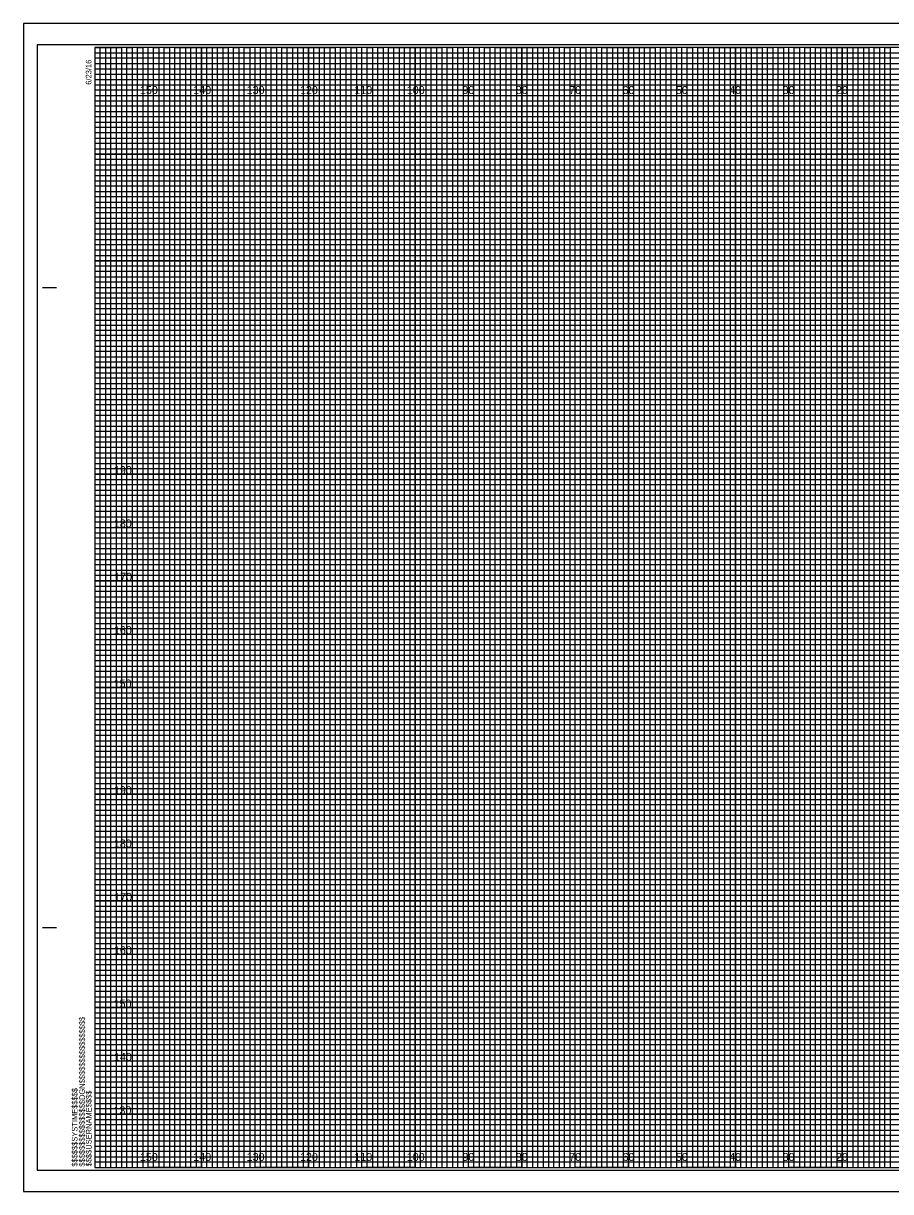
# Model space of a CAD drawing. Extents: x -13 to 323, y -5 to 4174.
# Drawn here: x -13.4 to 149.1, y 655.5 to 874.5 of the extents above; entities that cross this region are included whole.
import ezdxf

# ---------------------------------------------------------------- set-up
doc = ezdxf.new("R2010")
doc.units = 0
for name, color, linetype in [('Exist Cross Section Cell', 7, 'Continuous'), ('Exist XS Center Line Elevation Label', 7, 'Continuous'), ('Exist XS Ground Line', 7, 'Continuous'), ('Prop CMT Guardrail Graphics', 7, 'Continuous'), ('Prop CMT Pvmt Course 1', 7, 'Continuous'), ('Prop CMT Pvmt Course 2', 7, 'Continuous'), ('Prop CMT Pvmt Course 3', 7, 'Continuous'), ('Prop CMT Shld Paved Course 1', 7, 'Continuous'), ('Prop CMT Shld Paved Course 2', 7, 'Continuous'), ('Prop CMT Subgrade Earthwork', 7, 'Continuous'), ('Scratch_Level_0', 7, 'Continuous')]:
    doc.layers.add(name, color=color, linetype=linetype)

msp = doc.modelspace()

# ---------------------------------------------------------------- linework, layer by layer
at = {"layer": 'Exist XS Center Line Elevation Label'}
for points in [[(0, 870), (5, 870), (5, 660), (15, 660), (15, 870), (25, 870), (25, 660), (35, 660), (35, 870), (45, 870), (45, 660), (55, 660), (55, 870), (65, 870), (65, 660), (75, 660), (75, 870), (85, 870), (85, 660), (95, 660), (95, 870), (105, 870), (105, 660), (115, 660), (115, 870), (125, 870), (125, 660), (135, 660), (135, 870), (145, 870), (145, 660), (155, 660)], [(0, 865), (275, 865)], [(0, 845), (320, 845), (320, 855), (0, 855)], [(0, 825), (320, 825), (320, 835), (0, 835)], [(0, 805), (320, 805), (320, 815), (0, 815)], [(0, 785), (320, 785), (320, 795), (0, 795)], [(0, 765), (320, 765), (320, 775), (0, 775)], [(0, 745), (320, 745), (320, 755), (0, 755)], [(0, 725), (320, 725), (320, 735), (0, 735)], [(0, 705), (320, 705), (320, 715), (0, 715)], [(0, 685), (320, 685), (320, 695), (0, 695)], [(0, 665), (320, 665), (320, 675), (0, 675)]]:
    msp.add_lwpolyline(points, dxfattribs=at)
at = {"layer": 'Exist XS Ground Line'}
for p, q in [((10, 870), (0, 870)), ((10, 660), (10, 870)), ((30, 870), (20, 870)), ((20, 870), (20, 660)), ((30, 660), (30, 870)), ((50, 870), (40, 870)), ((40, 870), (40, 660)), ((50, 660), (50, 870)), ((70, 870), (60, 870)), ((60, 870), (60, 660)), ((70, 660), (70, 870)), ((90, 870), (80, 870)), ((80, 870), (80, 660)), ((90, 660), (90, 870)), ((110, 870), (100, 870)), ((100, 870), (100, 660)), ((110, 660), (110, 870)), ((130, 870), (120, 870)), ((120, 870), (120, 660)), ((130, 660), (130, 870)), ((150, 870), (140, 870)), ((140, 870), (140, 660)), ((20, 660), (10, 660)), ((40, 660), (30, 660)), ((60, 660), (50, 660)), ((80, 660), (70, 660)), ((100, 660), (90, 660)), ((120, 660), (110, 660)), ((140, 660), (130, 660))]:
    msp.add_line(p, q, dxfattribs=at)
for points in [[(0, 860), (320, 860), (320, 850), (0, 850)], [(0, 840), (320, 840), (320, 830), (0, 830)], [(0, 820), (320, 820), (320, 810), (0, 810)], [(0, 800), (320, 800), (320, 790), (0, 790)], [(0, 780), (320, 780), (320, 770), (0, 770)], [(0, 760), (320, 760), (320, 750), (0, 750)], [(0, 740), (320, 740), (320, 730), (0, 730)], [(0, 720), (320, 720), (320, 710), (0, 710)], [(0, 700), (320, 700), (320, 690), (0, 690)], [(0, 680), (320, 680), (320, 670), (0, 670)]]:
    msp.add_lwpolyline(points, dxfattribs=at)
at = {"layer": 'Prop CMT Pvmt Course 1'}
for p, q in [((323.3, 874.5), (-13.4, 874.5)), ((-13.4, 874.5), (-13.4, 655.5)), ((-13.4, 655.5), (323.3, 655.5))]:
    msp.add_line(p, q, dxfattribs=at)
at = {"layer": 'Prop CMT Pvmt Course 2'}
msp.add_lwpolyline([(-13.4, 655.5), (323.3, 655.5), (323.3, 874.5), (-13.4, 874.5)], close=True, dxfattribs=at)
at = {"layer": 'Prop CMT Pvmt Course 3'}
msp.add_lwpolyline([(-10.8, 659.5), (322.4, 659.5), (322.4, 870.5), (-10.8, 870.5)], close=True, dxfattribs=at)
at = {"layer": 'Prop CMT Shld Paved Course 1'}
for p, q in [((-9.8, 825), (-7.3, 825)), ((-9.7, 825), (-7.2, 825)), ((-9.8, 705), (-7.3, 705)), ((-9.7, 705), (-7.2, 705)), ((0, 660), (0, 660)), ((0, 660), (0, 660)), ((0, 660), (0, 660)), ((0, 660), (0, 660)), ((0, 660), (0, 660)), ((0, 660), (0, 660)), ((0, 660), (0, 660))]:
    msp.add_line(p, q, dxfattribs=at)
msp.add_lwpolyline([(320, 870), (0, 870), (0, 660), (320, 660)], close=True, dxfattribs=at)
at = {"layer": 'Prop CMT Shld Paved Course 2'}
for points in [[(0, 660), (1, 660), (1, 870), (2, 870), (2, 660)], [(2, 660), (3, 660), (3, 870), (4, 870), (4, 660)], [(5, 660), (6, 660), (6, 870), (7, 870), (7, 660)], [(7, 660), (8, 660), (8, 870), (9, 870), (9, 660)], [(10, 660), (11, 660), (11, 870), (12, 870), (12, 660)], [(12, 660), (13, 660), (13, 870), (14, 870), (14, 660)], [(15, 660), (16, 660), (16, 870), (17, 870), (17, 660)], [(17, 660), (18, 660), (18, 870), (19, 870), (19, 660)], [(20, 660), (21, 660), (21, 870), (22, 870), (22, 660)], [(22, 660), (23, 660), (23, 870), (24, 870), (24, 660)], [(25, 660), (26, 660), (26, 870), (27, 870), (27, 660)], [(27, 660), (28, 660), (28, 870), (29, 870), (29, 660)], [(30, 660), (31, 660), (31, 870), (32, 870), (32, 660)], [(32, 660), (33, 660), (33, 870), (34, 870), (34, 660)], [(35, 660), (36, 660), (36, 870), (37, 870), (37, 660)], [(37, 660), (38, 660), (38, 870), (39, 870), (39, 660)], [(40, 660), (41, 660), (41, 870), (42, 870), (42, 660)], [(42, 660), (43, 660), (43, 870), (44, 870), (44, 660)], [(45, 660), (46, 660), (46, 870), (47, 870), (47, 660)], [(47, 660), (48, 660), (48, 870), (49, 870), (49, 660)], [(50, 660), (51, 660), (51, 870), (52, 870), (52, 660)], [(52, 660), (53, 660), (53, 870), (54, 870), (54, 660)], [(55, 660), (56, 660), (56, 870), (57, 870), (57, 660)], [(57, 660), (58, 660), (58, 870), (59, 870), (59, 660)], [(60, 660), (61, 660), (61, 870), (62, 870), (62, 660)], [(62, 660), (63, 660), (63, 870), (64, 870), (64, 660)], [(65, 660), (66, 660), (66, 870), (67, 870), (67, 660)], [(67, 660), (68, 660), (68, 870), (69, 870), (69, 660)], [(70, 660), (71, 660), (71, 870), (72, 870), (72, 660)], [(72, 660), (73, 660), (73, 870), (74, 870), (74, 660)], [(75, 660), (76, 660), (76, 870), (77, 870), (77, 660)], [(77, 660), (78, 660), (78, 870), (79, 870), (79, 660)], [(80, 660), (81, 660), (81, 870), (82, 870), (82, 660)], [(82, 660), (83, 660), (83, 870), (84, 870), (84, 660)], [(85, 660), (86, 660), (86, 870), (87, 870), (87, 660)], [(87, 660), (88, 660), (88, 870), (89, 870), (89, 660)], [(90, 660), (91, 660), (91, 870), (92, 870), (92, 660)], [(92, 660), (93, 660), (93, 870), (94, 870), (94, 660)], [(95, 660), (96, 660), (96, 870), (97, 870), (97, 660)], [(97, 660), (98, 660), (98, 870), (99, 870), (99, 660)], [(100, 660), (101, 660), (101, 870), (102, 870), (102, 660)], [(102, 660), (103, 660), (103, 870), (104, 870), (104, 660)], [(105, 660), (106, 660), (106, 870), (107, 870), (107, 660)], [(107, 660), (108, 660), (108, 870), (109, 870), (109, 660)], [(110, 660), (111, 660), (111, 870), (112, 870), (112, 660)], [(112, 660), (113, 660), (113, 870), (114, 870), (114, 660)], [(115, 660), (116, 660), (116, 870), (117, 870), (117, 660)], [(117, 660), (118, 660), (118, 870), (119, 870), (119, 660)], [(120, 660), (121, 660), (121, 870), (122, 870), (122, 660)], [(122, 660), (123, 660), (123, 870), (124, 870), (124, 660)], [(125, 660), (126, 660), (126, 870), (127, 870), (127, 660)], [(127, 660), (128, 660), (128, 870), (129, 870), (129, 660)], [(130, 660), (131, 660), (131, 870), (132, 870), (132, 660)], [(132, 660), (133, 660), (133, 870), (134, 870), (134, 660)], [(135, 660), (136, 660), (136, 870), (137, 870), (137, 660)], [(137, 660), (138, 660), (138, 870), (139, 870), (139, 660)], [(140, 660), (141, 660), (141, 870), (142, 870), (142, 660)], [(142, 660), (143, 660), (143, 870), (144, 870), (144, 660)], [(145, 660), (146, 660), (146, 870), (147, 870), (147, 660)], [(147, 660), (148, 660), (148, 870), (149, 870), (149, 660)]]:
    msp.add_lwpolyline(points, dxfattribs=at)
at = {"layer": 'Prop CMT Subgrade Earthwork'}
for p, q in [((10, 660), (10, 870)), ((20, 660), (20, 870)), ((30, 660), (30, 870)), ((40, 660), (40, 870)), ((50, 660), (50, 870)), ((60, 660), (60, 870)), ((70, 660), (70, 870)), ((80, 660), (80, 870)), ((90, 660), (90, 870)), ((100, 660), (100, 870)), ((110, 660), (110, 870)), ((120, 660), (120, 870)), ((130, 660), (130, 870)), ((140, 660), (140, 870)), ((0, 860), (320, 860)), ((0, 850), (320, 850)), ((0, 840), (320, 840)), ((0, 830), (320, 830)), ((0, 820), (320, 820)), ((0, 810), (320, 810)), ((0, 800), (320, 800)), ((0, 790), (320, 790)), ((0, 780), (320, 780)), ((0, 770), (320, 770)), ((0, 760), (320, 760)), ((0, 750), (320, 750)), ((0, 740), (320, 740)), ((0, 730), (320, 730)), ((0, 720), (320, 720)), ((0, 710), (320, 710)), ((0, 700), (320, 700)), ((0, 690), (320, 690)), ((0, 680), (320, 680)), ((0, 670), (320, 670))]:
    msp.add_line(p, q, dxfattribs=at)
at = {"layer": 'Scratch_Level_0'}
for p, q in [((0, 869), (260, 869)), ((260, 867.98), (0, 867.98)), ((0, 867.98), (0, 867)), ((0, 867), (260, 867)), ((260, 865.89), (0, 865.89)), ((0, 865.89), (0, 864)), ((0, 864), (320, 864))]:
    msp.add_line(p, q, dxfattribs=at)
for points in [[(0, 863), (270, 863), (320, 863), (320, 862), (0, 862)], [(0, 861), (320, 861), (320, 859), (0, 859)], [(0, 858), (320, 858), (320, 857), (0, 856.98)], [(0, 856), (320, 856), (320, 854), (0, 854)], [(0, 853), (320, 853), (320, 852), (0, 852)], [(0, 851), (320, 851), (320, 849), (0, 849)], [(0, 848), (320, 848), (320, 847), (0, 847)], [(0, 846), (320, 846), (320, 844), (0, 844)], [(0, 843), (320, 843), (320, 842), (0, 842)], [(0, 841), (320, 841), (320, 839), (0, 839)], [(0, 838), (320, 838), (320, 837), (0, 837)], [(0, 836), (320, 836), (320, 833.95), (320, 833), (320, 832), (0, 832)], [(0, 834), (320, 834), (320, 833), (0, 833)], [(0, 831), (320, 831), (320, 829), (0, 829.03)], [(0, 829.03), (320, 829), (320, 828), (0, 828)], [(0, 827), (320, 827), (320, 826), (0, 826)], [(0, 824), (320, 824), (320, 823), (0, 823)], [(0, 822), (320, 822), (320, 821), (0, 821)], [(-0.07, 818.89), (320, 818.89), (320, 817.88), (-0.07, 817.88)], [(0, 817), (320, 817), (320, 816), (0, 816)], [(0, 814), (320, 814), (320, 813), (0, 813)], [(0, 812), (320, 812), (320, 811), (0, 811)], [(0, 809), (320, 809), (320, 808), (0, 808)], [(0, 807), (320, 807), (320, 806), (0, 806)], [(0, 804), (320, 804), (320, 803), (0, 803)], [(0, 802), (320, 802), (320, 801), (0, 801)], [(0, 799), (320, 799), (319.99, 797.98), (0, 798)], [(0, 797), (320, 797), (320, 796), (0, 796)], [(0, 794), (320, 794), (320, 793), (0, 793)], [(0, 792), (320, 792), (320, 791), (0, 791)], [(0, 789), (320, 789), (320, 788), (0, 788)], [(0, 787), (320, 787), (320, 786), (0, 786)], [(0, 784), (320, 784), (320, 783), (0, 783)], [(0, 782), (320, 782), (320, 781), (0, 781)], [(0, 779), (320, 779), (320, 778), (0, 778)], [(0, 776.99), (320.07, 776.91), (320, 776), (0, 776)], [(0, 774), (320, 774), (320, 773), (0, 773)], [(0, 772), (320, 772), (320, 771), (0, 771)], [(0, 769), (320, 769), (320, 768), (0, 768)], [(0, 767), (320, 767), (320, 766), (0, 766)], [(0, 764), (320, 764), (320, 763), (0, 763)], [(0, 762), (320, 762), (320, 761), (0, 761)], [(0, 759), (320, 759), (320, 758), (0, 758)], [(0, 757), (320, 757), (320, 756), (0, 756)], [(0, 754), (320, 754), (320, 753), (0, 753)], [(0, 752), (320, 752), (320, 751), (0, 751)], [(0, 749), (320, 749), (320, 748), (0, 748)], [(0, 747), (320, 747), (320, 746), (0, 746)], [(0, 744), (320, 744), (320, 743), (0, 743)], [(0, 742), (320, 742), (320, 741), (0, 741)], [(0, 739), (320, 739), (319.99, 737.98), (0, 738)], [(0, 737), (320, 737), (320, 736), (0, 736)], [(0, 734), (320, 734), (320, 733), (0, 733)], [(0, 732), (320, 732), (320, 731), (0, 731)], [(0, 729), (320, 729), (320, 728), (0, 728)], [(0, 727), (320, 727), (320, 726), (0, 726)], [(0, 724), (320, 724), (320, 723), (0, 723)], [(0, 722), (320, 722), (320, 721), (0, 721)], [(0, 719), (320, 719), (320, 718), (0, 718)], [(0, 716.99), (320.07, 716.91), (320, 716), (0, 716)], [(0, 714), (320, 714), (320, 713), (0, 713)], [(0, 712), (320, 712), (320, 711), (0, 711)], [(0, 709), (320, 709), (320, 708), (0, 708)], [(0, 707), (320, 707), (320, 706), (0, 706)], [(0, 704), (320, 704), (320, 703), (0, 703)], [(0, 702), (320, 702), (320, 701), (0, 701)], [(0, 699), (320, 699), (320, 698), (0, 698)], [(0, 697), (320, 697), (320, 696), (0, 696)], [(0, 694), (320, 694), (320, 693), (0, 693)], [(0, 692), (320, 692), (320, 691), (0, 691)], [(0, 689), (320, 689), (320, 688), (0, 688)], [(0, 687), (320, 687), (320, 686), (0, 686)], [(0, 684), (320, 684), (320, 683), (0, 683)], [(0, 682), (320, 682), (320, 681), (0, 681)], [(0, 679), (320, 679), (320, 678), (0, 678)], [(0, 677), (320, 677), (320, 676), (0, 676)], [(0, 674), (320, 674), (320, 673), (0, 673)], [(0, 672), (320, 672), (320, 671), (0, 671)], [(0, 669), (320, 669), (320, 668), (0, 668)], [(0, 667), (320, 667), (320, 666), (0, 666)], [(0, 664), (320, 664), (320, 663), (0, 663)], [(0, 662), (320, 662), (320, 661), (0, 661)]]:
    msp.add_lwpolyline(points, dxfattribs=at)

# ---------------------------------------------------------------- texts
at = {"layer": 'Exist Cross Section Cell'}
for s, p in [('150', (8.44, 861.25)), ('140', (18.44, 861.25)), ('130', (28.44, 861.25)), ('120', (38.44, 861.25)), ('110', (48.62, 861.25)), ('100', (58.44, 861.25)), ('90', (68.86, 861.25)), ('80', (78.86, 861.25)), ('70', (88.86, 861.25)), ('60', (98.86, 861.25)), ('50', (108.86, 861.25)), ('40', (118.86, 861.25)), ('30', (128.86, 861.25)), ('20', (138.86, 861.25)), ('150', (8.44, 661.25)), ('140', (18.44, 661.25)), ('130', (28.44, 661.25)), ('120', (38.44, 661.25)), ('110', (48.62, 661.25)), ('100', (58.44, 661.25)), ('90', (68.86, 661.25)), ('80', (78.86, 661.25)), ('70', (88.86, 661.25)), ('60', (98.86, 661.25)), ('50', (108.86, 661.25)), ('40', (118.86, 661.25)), ('30', (128.86, 661.25)), ('20', (138.86, 661.25))]:
    msp.add_text(s, height=1.5, dxfattribs=at).set_placement(p)
at = {"layer": 'Prop CMT Guardrail Graphics'}
for s, p in [('190', (3.57, 790)), ('180', (3.55, 780)), ('170', (3.61, 770)), ('160', (3.57, 760)), ('150', (3.52, 750)), ('190', (3.57, 730)), ('180', (3.55, 720)), ('170', (3.61, 710)), ('160', (3.57, 700)), ('150', (3.52, 690)), ('140', (3.57, 680)), ('130', (3.49, 670))]:
    msp.add_text(s, height=1.5, dxfattribs=at).set_placement(p)
at = {"layer": 'Prop CMT Shld Paved Course 1'}
for s, p in [('6/23/16', (-0.65, 863)), ('$$$$$$$$$$$$$$$$DGN$$$$$$$$$$$$$$$$', (-1.88, 660.18)), ('$$$$$$SYSTIME$$$$$', (-3.26, 660.18)), ('$$$$USERNAME$$$$', (-0.62, 660.23))]:
    msp.add_text(s, height=1.05, rotation=90, dxfattribs=at).set_placement(p)

doc.saveas('drawing.dxf')
